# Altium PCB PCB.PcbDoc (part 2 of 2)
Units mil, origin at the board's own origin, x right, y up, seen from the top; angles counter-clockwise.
Board outline 1610 x 1385 mil, 4 copper layers (Top Layer, Signal Layer 1, Signal Layer 2, Bottom Layer), stack 61.2 mil thick; 53 components, 26 nets, 134 pads, 40 vias.
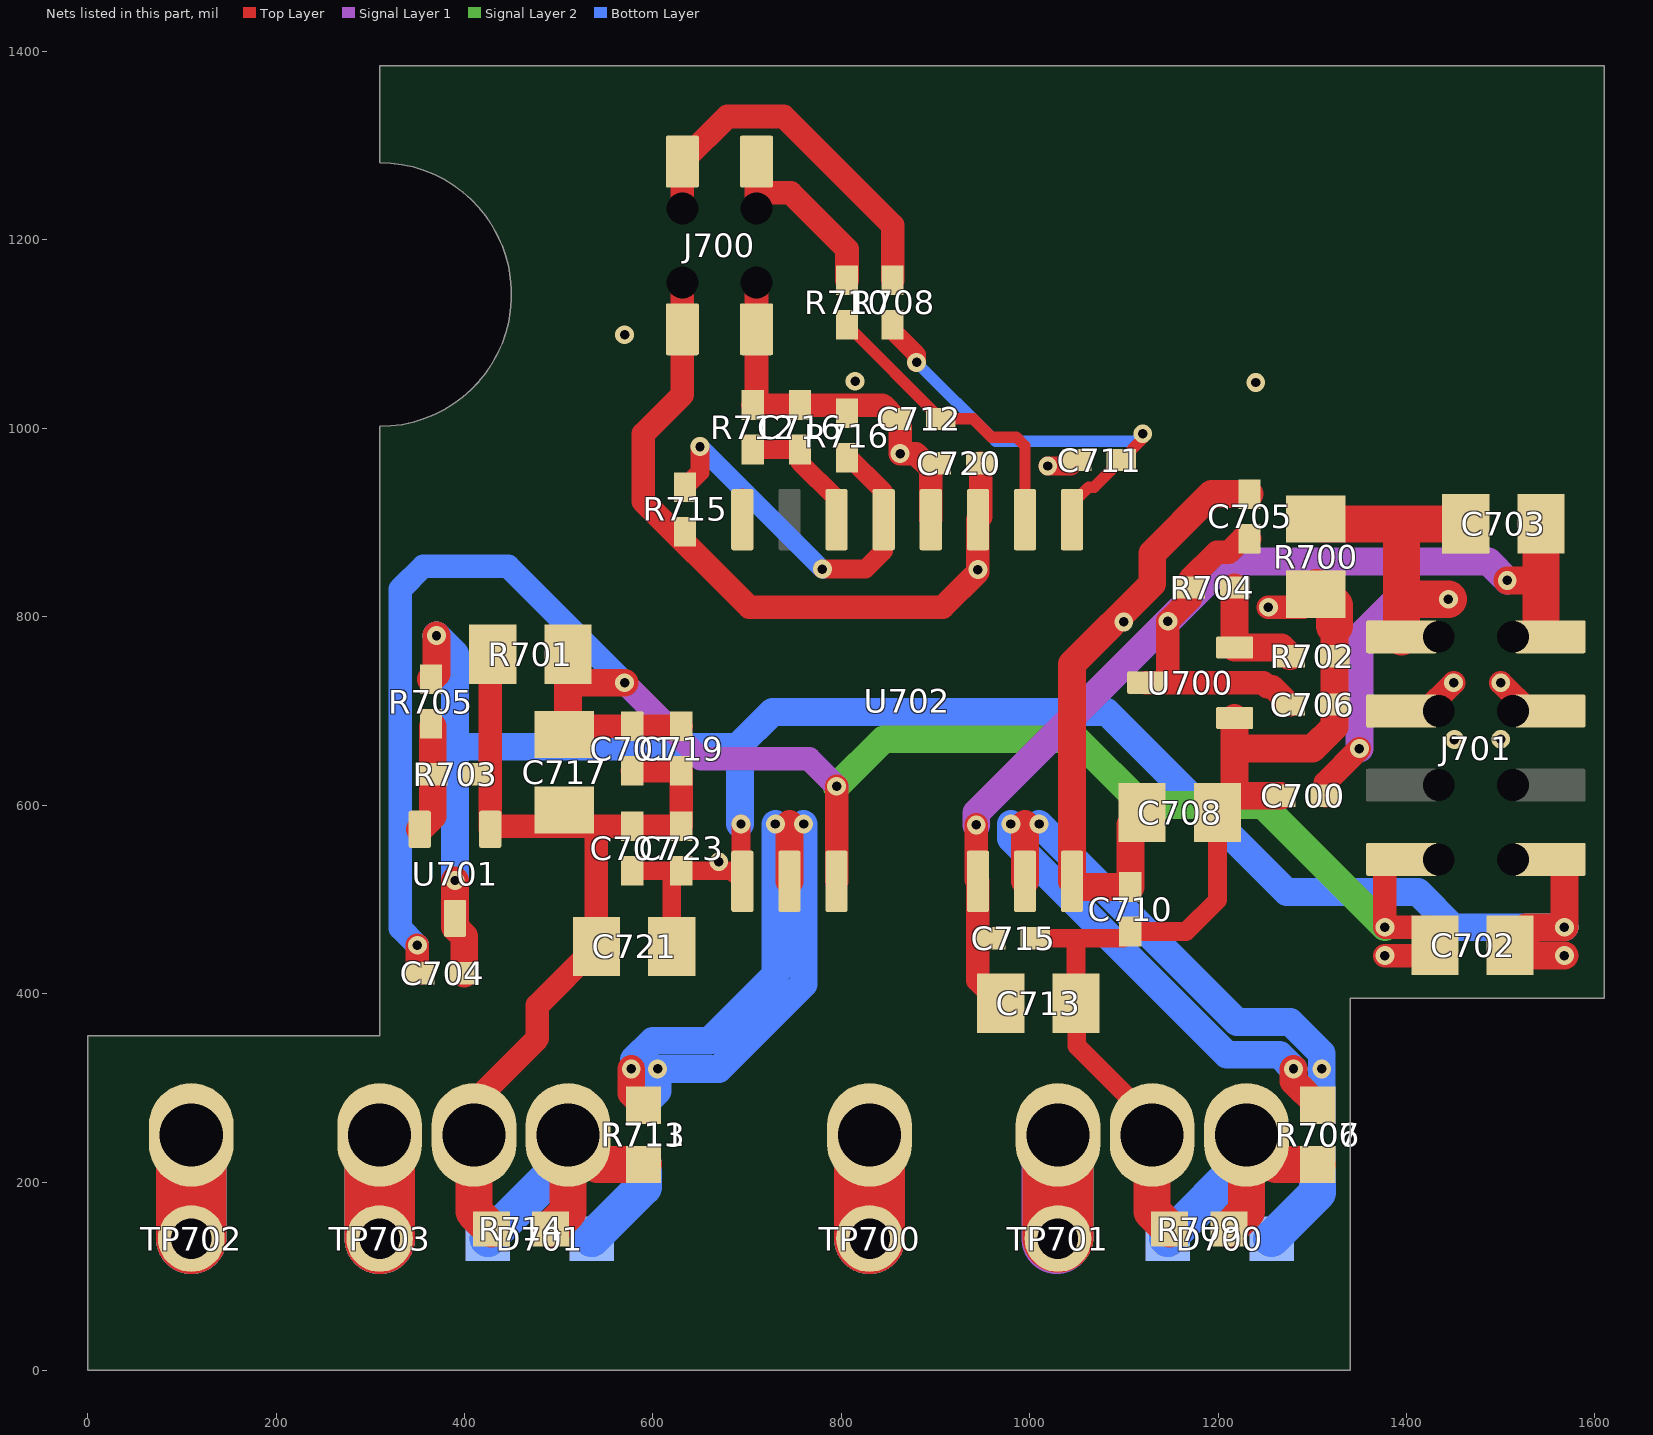
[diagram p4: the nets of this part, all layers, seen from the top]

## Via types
v1: diameter 20, hole 10, Top Layer to Bottom Layer, 40 vias

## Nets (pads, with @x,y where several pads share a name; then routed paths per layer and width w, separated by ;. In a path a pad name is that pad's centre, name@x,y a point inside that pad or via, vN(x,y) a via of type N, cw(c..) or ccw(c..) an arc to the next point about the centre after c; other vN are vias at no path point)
5Vp: C720.1 J700.2 J700.@631.26,1154.71 J701.4 pad.1@1434.13,699.99 R715.2 U702.3 U702.8 | length 850.8
  Top Layer w20: U702.8@693.58,904.42 U702.8@695,903 U702.8@695,926.07
  Top Layer w25: J700.@631.26,1154.71 J700.2@631.26,1105.1 631.26,1035.41 590,994.15 590,922.46 702.46,810 907.49,810 945,847.51 v1(945,850) U702.3@945,903 948.14,906.14 C720.1@948.14,963 ; J701.4@1419.99,699.99 v1(1450,730)
  other v1: 1450.81,669.61 570,1099.23
+VA: C700.1 C703.1 C705.1 C708.1 C710.1 J701.2 pad.1@1434.13,778.73 R700.2 U702.16 | length 1256.9
  Top Layer w25: C700.1@1313.62,610 1313.62,623.62 v1(1350,660)
  Top Layer w29.53: U702.16@1045,519.14 1045,749.98 1130,834.98 1130,867.2 1192.92,930.12 C705.1@1233.34,930.12 ; U702.16@1050.94,513.21 C710.1@1106.82,513.21 C708.1@1106.82,579.62
  Top Layer w39.37: R700.2@1303.78,903.83 1309.07,898.54 1394.56,898.54 ; J701.2@1394.56,778.73 1394.56,898.54 ; 1398.05,818.54 v1(1444.37,818.54) ; C703.1@1462.87,898.54 1394.56,898.54
  Signal Layer 1 w29.53: v1(1350,660) 1350,778.54 1390,818.54 v1(1444.37,818.54)
  other v1: 1099.86,794.59
+VB: C701.1 C702.1 C704.1 C717.1 C719.1 J701.8 pad.1@1434.13,542.51 R701.2 U702.11 | length 2187.7
  Top Layer w25: v1(350,451.35) 350,424.06 C704.1@352.6,421.46 ; C717.1@510,679 514.62,683.62 C701.1@578.19,683.62 C719.1@630,683.62 ; U702.11@795,519.14 v1(795,620) ; v1(1377.02,440.38) 1416.87,440.38 1436,459.51 1425.13,470.38 v1(1377.02,470.38) J701.8@1377.02,532.22
  Top Layer w29.53: C717.1@510,679 R701.2@510,730 ; R701.2@520,730 v1(570,730)
  Signal Layer 1 w25: v1(570,730) 650.83,649.17 765.83,649.17 v1(795,620)
  Signal Layer 2 w29.53: v1(795,620) 845,670 1050,670 1120,600 1247.4,600 v1(1377.02,470.38)
  Bottom Layer w25: v1(350,451.35) 332,469.35 332,829.35 356.25,853.61 446.39,853.61 v1(570,730)
-VA: C703.2 C705.2 C706.2 C713.2 C715.2 J701.1 pad.1@1512.87,778.73 R704.1 U700.3 U702.14 | length 1391.3
  Top Layer w25: v1(943.31,579) 943.31,520.84 U702.14@945,519.14 945,414.07 C713.2@969.21,389.86 ; U700.3@1123.04,730 1248.01,730 1252.19,725.82 1257.28,725.82 C706.2@1276.38,706.72 ; 1146.66,735.01 v1(1146.66,795.18) 1170.29,818.81 R704.1@1170.29,830.93 1170.29,840.06 1198.78,868.54 1211.39,868.54 1225.72,882.87 C705.2@1233.34,882.87
  Top Layer w29.53: v1(1506.87,838.54) 1534.32,838.54
  Top Layer w39.37: J701.1@1542.87,788.3 C703.2@1542.87,898.54
  Signal Layer 1 w29.53: v1(943.31,579) 943.31,591.83 v1(1146.66,795.18) 1210.02,858.54 1486.87,858.54 v1(1506.87,838.54)
-VB: C702.2 C704.2 C707.2 C721.2 C723.2 J701.7 pad.1@1512.87,542.51 R705.1 U701.3 U702.9 | length 2233.3
  Top Layer w20: C707.2@578.19,530.38 C723.2@630,530.38 ; C721.2@620,450 620,520.38 C723.2@630,530.38 ; v1(693.58,580) U702.9@693.58,520.56 ; U702.9@695,519.14 U702.9@693.58,520.56 ; C723.2@630,530.38 683.77,530.38 U702.9@693.58,520.56
  Top Layer w29.53: R705.1@364.41,733.62 370.31,739.53 v1(370.31,780) ; v1(390,520) U701.3@390,479.9 390,470.71 399.84,460.87 C704.2@399.84,421.46 ; v1(1567.5,440.38) 1535.13,440.38 1516,459.51 1526.87,470.38 v1(1567.5,470.38) J701.7@1567.5,540.68
  Bottom Layer w29.53: v1(370.31,780) 390,760.31 v1(390,520) ; 398,662 690,662 ; v1@692.6,580 692.6,659.4 690,662 ; v1(1567.5,470.38) 1449.52,470.38 1412.12,507.78 1272.83,507.78 1081.73,698.88 726.88,698.88 690,662
  other v1: 670,540
Coma: C700.2 C706.1 C708.2 C710.2 C713.1 C715.1 pad.1@1130,250 R700.1 R702.2 R709.1 U700.1 | length 1070.5
  Top Layer w20: C715.1@1005.91,458.72 1099.58,458.72 C710.2@1106.82,465.96 1165.96,465.96 1199.34,499.34 C708.2@1199.34,592.14 ; 1049.21,457 C713.1@1049.21,389.86 1050,389.07 1050,344.5 pad.1@1130,264.5
  Top Layer w25: v1(1253.28,810.13) R700.1@1290.08,810.13
  Top Layer w29.53: C708.2@1199.34,592.14 C708.2@1217.2,610 ; U700.1@1217.53,692.6 1217.53,660 ; C700.2@1266.38,610 C708.2@1217.2,610 ; 1323.62,790 C706.1@1323.62,706.72 1323.62,683.31 1300.31,660 1217.53,660 ; C708.2@1217.2,610 1217.53,610.33 1217.53,660
  Top Layer w39.37: pad.1@1130,218.5 1130,168.5 R709.1@1148.5,150 ; R700.1@1304.46,830.93 1323.62,811.77 1323.62,790
Comb: C701.2 C707.1 C717.2 C719.2 C721.1 C723.1 pad.1@410,250 R701.1 R703.2 R714.1 U701.1 | length 992.8
  Top Layer w25: pad.1@410,250 410,285 477.46,352.46 477.46,387.46 C721.1@540,450 540,571.62 546,577.62 ; R701.1@430,760 427.4,757.4 U701.1@427.4,574.39 430.64,577.62 546,577.62 ; C701.2@578.19,636.38 C719.2@630,636.38 C723.1@630,577.62 C707.1@578.19,577.62 546,577.62
  Top Layer w39.37: pad.1@410,250 410,168.5 R714.1@428.5,150
NetC711_1: C711.1 R708.2 U702.1 | length 454.1
  Top Layer w12: U702.1@1045,903 1045,919.88 1062.57,937.45 1068.35,937.45 C711.1@1097.24,966.35 1120.02,989.12 v1(1120.02,994.15)
  Top Layer w20: R708.2@854.41,1110 854.41,1103.7 880,1078.11 v1(880,1070)
  Bottom Layer w12: v1(880,1070) 963.63,986.37 1112.24,986.37 v1(1120.02,994.15)
NetC712_1: C712.1 R710.2 U702.2 | length 338.8
  Top Layer w12: R710.2@806.05,1109.54 C712.1@905.59,1010 940,1010 959.48,990.52 985.85,990.52 995,981.37 U702.2@995,903
  Top Layer w20: U702.2@995,884.61 U702.2@995,903
NetC716_1: C716.1 R712.2 U702.6 | length 127.1
  Top Layer w20: R712.2@706.05,977.45 C716.1@756.05,977.45 ; C716.1@756.05,963.95 795,925 U702.6@795,903
NetD700_1: D700.1 R707.2 | length 98.8
  Bottom Layer w39.37: D700.1@1256.77,140 1305.66,188.88 R707.2@1305.66,218.5
NetD701_1: D701.1 R713.2 | length 101.2
  Bottom Layer w39.37: D701.1@535.12,140 590,194.88 R713.2@590,218.5
NetR702_1: R702.1 R704.2 U700.2 | length 126.3
  Top Layer w29.53: R704.2@1217.53,830.93 U700.2@1217.53,767.4 1266.98,767.4 R702.1@1276.38,758
NetR703_1: R703.1 R705.2 U701.2 | length 114.9
  Top Layer w29.53: U701.2@352.6,574.39 366.38,588.17 R703.1@366.38,632.8 R705.2@366.38,683.62
NetR706_1: R706.1 R707.1 U702.15 | length 984.5
  Top Layer w29.53: U702.15@995,519.14 995,580 ; v1(1280,320) 1280,307.15 R706.1@1305.66,281.5
  Bottom Layer w29.53: v1(980,580) 980,564.48 1209.48,335 1265,335 v1(1280,320) ; v1(1010,580) 1220,370 1276.52,370 1310,336.52 v1(1310,320) 1310,285.84 R707.1@1305.66,281.5
NetR711_1: R711.1 R713.1 U702.10 | length 859
  Top Layer w29.53: v1(577,320) 577,294.5 R711.1@590,281.5 ; U702.10@745,519.14 745,580
  Bottom Layer w29.53: 580,330 600,350 660,350 730,420 v1(730,580) ; R713.1@590,281.5 604.99,296.49 v1(604.99,320) 670,320 760,410 v1(760,580)
NetR715_1: R715.1 R716.2 U702.5 | length 395.6
  Top Layer w20: R715.1@634.11,937.45 650,953.34 v1(650,980.6) ; v1(780,850.6) 825.6,850.6 845,870 U702.5@845,903 ; R716.2@806.05,971.4 U702.5@845,932.45
  Bottom Layer w20: v1(650,980.6) v1(780,850.6) v1@780.6,850
PGND: C711.2 C712.2 C716.2 C720.2 J700.4 J700.@710,1154.71 J701.3 pad.1@1512.87,699.99 R712.1 R716.1 U702.4 | length 508.9
  Top Layer w20: v1(1019.13,960) 1043.65,960 C711.2@1050,966.35
  Top Layer w25: R712.1@706.05,1024.69 806.05,1024.69 843.65,1024.69 C712.2@858.35,1010 ; R712.1@710,1028.65 J700.4@710,1105.1 J700.@710,1154.71 ; C712.2@862.42,1005.93 v1(862.42,973.2) 878.91,973.2 895,957.11 U702.4@895,903 ; v1(1500,730) 1530.01,699.99 J701.3@1552.44,699.99
  other v1: 1500,670 1240,1048.6 814.71,1050
VDA: pad.1@830,250 TP700.1 | length 440
  Top Layer w75: TP700.1@830,140 pad.1@830,250
  Signal Layer 1 w75: TP700.1@830,140 pad.1@830,250
  Signal Layer 2 w75: TP700.1@830,140 pad.1@830,250
  Bottom Layer w75: TP700.1@830,140 pad.1@830,250
VDB: pad.1@110,250 TP702.1 | length 440
  Top Layer w75: TP702.1@110,140 pad.1@110,250
  Signal Layer 1 w75: TP702.1@110,140 pad.1@110,250
  Signal Layer 2 w75: TP702.1@110,140 pad.1@110,250
  Bottom Layer w75: TP702.1@110,140 pad.1@110,250
Vg1: J700.1 J700.@631.26,1233.45 R708.1 | length 398.8
  Top Layer w25: J700.@631.26,1233.45 J700.1@631.26,1283.05 679.19,1330.99 739.01,1330.99 854.41,1215.59 R708.1@854.41,1157.24
Vg2: J700.3 J700.@710,1233.45 R710.1 | length 203.4
  Top Layer w25: J700.@710,1233.45 710,1250 ; J700.3@710,1283.05 710,1250 ; R710.1@806.05,1157.24 806.05,1190.16 746.2,1250 710,1250
VGA: D700.2 pad.1@1230,250 R706.2 R709.2 | length 314.4
  Top Layer w39.37: R709.2@1211.5,150 1230,168.5 pad.1@1230,250 1261.5,218.5 R706.2@1305.66,218.5
  Bottom Layer w39.37: D700.2@1146.54,140 pad.1@1230,223.46
VGB: D701.2 pad.1@510,250 R711.2 R714.2 | length 321.1
  Top Layer w39.37: R714.2@491.5,150 510,168.5 pad.1@510,250 541.5,218.5 R711.2@590,218.5
  Bottom Layer w39.37: D701.2@424.88,140 pad.1@510,225.12
VSA: pad.1@1030,250 TP701.1 | length 434.2
  Top Layer w75: TP701.1@1030,141.46 pad.1@1030,250
  Signal Layer 1 w75: TP701.1@1028.54,140 pad.1@1028.54,248.54
  Signal Layer 2 w75: TP701.1@1030,141.46 pad.1@1030,250
  Bottom Layer w75: TP701.1@1030,141.46 pad.1@1030,250
VSB: pad.1@310,250 TP703.1 | length 440
  Top Layer w75: TP703.1@310,140 pad.1@310,250
  Signal Layer 1 w75: TP703.1@310,140 pad.1@310,250
  Signal Layer 2 w75: TP703.1@310,140 pad.1@310,250
  Bottom Layer w75: TP703.1@310,140 pad.1@310,250
pads on no net: J701.5 J701.6 U702.7

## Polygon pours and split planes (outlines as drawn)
5Vp on Top Layer "5Vp" (solid, pour order 0): 1363.56,659.4 1457.12,659.4 1462.87,665.15 1462.87,730 1452.87,740 1414.18,740 1363.56,689.37
+VB on Top Layer "+VB" (solid, pour order 2): 1360,560 1350,550 1350,420 1360,410 1440,410 1450,420 1450,550 1440,560
-VB on Top Layer "-VB" (solid, pour order 4): 1500,410 1490,420 1490,550 1500,560 1580,560 1590,550 1590,420 1580,410
-VA on Top Layer "-VA" (solid, pour order 6): 1530,950 1520,940 1520,868.54 1500,848.54 1496.87,848.54 1496.87,783.13 1520,760 1590,760 1600,770 1600,940 1590,950
Coma on Top Layer "COMA" (solid, pour order 8): 1160,110 1170,120 1170,250 1170.29,332.28 1280,441.99 1280,611.48 1350,681.48 1350,840 1340,850 1217.69,850 1206.1,838.41 1206.1,709.81 1180,683.71 1180,530 1130,480 1010.78,480 996.07,465.29 996.07,433.79 1020,409.86 1020,357.87 1087.87,290 1087.87,122.13 1100,110
PGND on Top Layer "PGND" (solid, pour order 14): 1500,740 1490,730 1490,666.27 1496.27,660 1560,660 1590,690 1590,720 1570,740
+VA on Top Layer "+VA" (solid, pour order 16): 1480,870 1490,880 1490,940 1449.4,980.6 1210.89,980.6 1170.29,940 1115.23,884.94 1115.23,839.64 1031.48,755.89 1031.48,513 1045.14,499.34 1109.34,499.34 1150,540 1150,699.87 1217.53,767.4 1467.4,767.4 1480,780
Comb on Top Layer "COMB" (solid, pour order 26): 410,783.73 410,740 400,730 400,557.78 427.4,530.38 427.4,397.4 370.31,340.31 370.31,160.69 401,130 439.49,130 450,140.51 450,280 560,390 560,553.62 566.38,560 624.35,560 640,575.65 640,640 630,650 566.54,650 551.54,635 481,635 466,650 466,777.73 460,783.73
VGB on Top Layer "VGB" (solid, pour order 28): 480,289.62 470,279.62 470,141.3 480,131.3 552.32,131.3 610,188.98 610,220 590,240 570,240 570,240.44 520,290.44
VGA on Top Layer "VGA" (solid, pour order 30): 1199.73,120.27 1190.16,129.84 1190,263.24 1217.2,290.44 1218.02,289.62 1250,289.62 1250,286.96 1286.96,250 1324.36,250 1334.2,240 1334.2,184.2 1270.27,120.27
5Vp on Top Layer "5VP" (solid, pour order 32): 670,1160 660,1170 589.73,1170 560,1140.27 560,920.93 683.16,797.77 923.47,797.77 960,834.29 960,930 926.96,963.04 918.93,963.04 918.93,961.97 916.96,960 918.93,958.03 918.93,857.96 891.2,830.22 891.2,829.42 744.14,829.42 710,863.56 710,920.6 670,960.6
PGND on Top Layer "PGND" (solid, pour order 40): 700,1170 690,1160 690,1019.83 700,1009.83 700.17,1010 790,1010 870,930 870,880 880,870 900,870 910,880 910,989.37 730,1169.37
+VB on Top Layer "+VB" (solid, pour order 54): 490,788.54 480,778.54 480,678.31 497.72,660.59 530,660.59 530.59,660 640,660 690,610 750.15,610 780,580.15 780,500 790,490 810,490 820,500 820,629.47 729.47,720 645.3,720 577,788.3
-VB on Top Layer "-VB" (solid, pour order 58): 710,579.62 699.62,590 677.81,590 641.81,554 570.38,554 566.38,550 566.38,492.17 580,478.54 580,433.44 591.99,421.46 629.39,421.46 710,502.07
NetR711_1 on Top Layer "R711_1" (solid, pour order 60): 720,590 710,580 710,490.31 559.65,339.96 559.65,270 569.65,260 608.7,260 639.04,290.33 770,421.3 770,576.05 756.05,590
-VA on Top Layer "-VA" (solid, pour order 62): 952.14,600 960,592.14 960,516.42 980,496.42 980,457.07 1000,437.07 1000,359.86 990,349.86 940.14,349.86 930,360 930,593.36 936.64,600
-VB on Bottom Layer "-VB" (solid, pour order 38): 1580,410 1490,410 1444.41,455.59 1444.41,460 1404.35,500 1220,500 1070,650 771.15,650 710,588.85 710,550 660,500 382.14,500 360,522.14 360,810 440,730 1122,730 1295.11,556.89 1571.46,556.89 1590.33,538.02 1590.33,420
NetR706_1 on Bottom Layer "R706_1" (solid, pour order 36): 980,600 970,590 970,556.89 970.41,556.89 1202.29,325 1254.19,325 1293.35,285.84 1317.61,285.84 1321.77,290 1321.77,345.26 1287.02,380 1230,380 1010,600
NetR711_1 on Bottom Layer "R711_1" (solid, pour order 34): 730,600 720,590 720,430 650,360 593.48,360 562.8,329.32 562.8,268.5 571.3,260 630,260 775.04,405.04 775.04,590.7 765.74,600
+VB on Bottom Layer "+VB" (solid, pour order 10): 1360,560 1305.66,505.66 1305.66,464.34 1360,410 1440,410 1450,420 1450,550 1440,560
PGND on Bottom Layer "PGND" (solid, pour order 44): 680,1160 680,1146.85 680,1146.33 680,1051.51 842.09,889.42 1290,889.42 1290,866.27 1496.27,660 1570,660 1600,690 1600,1120 1350,1370 890,1370
5Vp on Bottom Layer "5VP" (solid, pour order 18): 1457.12,659.4 1462.59,664.88 1462.59,757.41 1310,910 880,910 670,1120 670,1160 660,1170 589.73,1170 580,1160.27 580,1070 820,830 1243.76,830 1414.35,659.4
NetR711_1 on Signal Layer 1 "R711_1" (solid, pour order 70): 722.14,590 712.14,580 712.14,490.31 561.79,339.96 561.79,270 571.79,260 610.84,260 641.18,290.33 772.14,421.3 772.14,576.05 758.19,590
Coma on Signal Layer 1 "COMA" (solid, pour order 42): 1160,110 1170,120 1170,250 1170.29,332.28 1280,441.99 1280,611.48 1310,641.48 1310,810 1300,820 1247.53,820 1206.1,778.57 1206.1,709.81 1180,683.71 1180,554.84 1105.16,480 1087.87,462.71 1087.87,290 1087.87,122.13 1100,110
PGND on Signal Layer 1 "PGND" (solid, pour order 46): 680,1160 680,1146.85 680,1146.33 680,1051.51 842.09,889.42 1114.42,889.42 1267.5,1042.5 1131.77,1178.23 698.23,1178.23
-VA on Signal Layer 1 "-VA" (solid, pour order 48): 930,570 935.67,564.33 950,564.33 965.67,580 1070,580 1200,710 1200,808.93 1221.07,830 1520,830 1530,840 1530,900 1520,910 1242.26,910 930,597.74
+VA on Signal Layer 1 "+VA" (solid, pour order 50): 1470,822.03 1469.86,822.03 1461.9,830 1390,830 1340,780 1340,650 1350,640 1383.76,640 1393.76,650 1393.76,734.72 1469.16,810.13
-VB on Signal Layer 1 "-VB" (solid, pour order 72): 710,580 700,590 630,590 420,800 370,800 360,790 360,520 380.42,499.58 652.57,499.58 709.41,556.43
NetR711_1 on Signal Layer 2 "R711_1" (solid, pour order 68): 722.14,590 712.14,580 712.14,490.31 561.79,339.96 561.79,270 571.79,260 610.84,260 641.18,290.33 772.14,421.3 772.14,576.05 758.19,590
+VA on Signal Layer 2 "+VA" (solid, pour order 52): 1080,800.02 1100.02,780 1429.87,780 1460,810.13 1460,840 1380,920 1116.23,920 1080,883.77
+VB on Signal Layer 2 "+VB" (solid, pour order 66): 1390,410 1400,420 1400,500 1238.9,661.1 1113.74,661.1 1044.84,730 634.99,730 604.99,760 500,760 321.1,581.1 321.1,448.9 340,430 620,430 840,650 1031.84,650 1271.84,410

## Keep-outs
Keep-Out Layer:
  text ".Layer_Name" at 577,-858.49 h60

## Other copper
Top Layer:
  text ".Layer_Name" at 577,-858.49 h60
Bottom Layer:
  text ".Layer_Name" at 577,-858.49 h60

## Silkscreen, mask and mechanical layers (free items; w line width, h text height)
Top Overlay:
  lines w10: 340,780 330,790 330,810.83 330.94,811.77 360,811.77 ; 430,470.71 449.06,451.65 449.06,398.36 487.41,360 510,360 ; 541.5,960 541.5,1000 570.14,1028.65 660,1028.65 ; 550,1330 550.14,1330 570.14,1350 736.05,1350 756.05,1330 756.05,1090.5 776.55,1070 845.59,1070 865.59,1050 ; 679.19,450 709.19,420 745,420 ; 900.66,360 910,369.34 910,370 910,420 920,430 ; 1300,961.1 1300,1009.69 1329.38,1039.07 1330.42,1039.07 ; 1320,1380 1320,1049.49 1340.85,1028.65 1600,1028.65
  text ".Layer_Name" at 577,-858.49 h60
Bottom Overlay:
  text "PMP22001 RevA" at 1360,690 h108.27
  text ".Layer_Name" at 577,-858.49 h60
Top Paste:
  text ".Layer_Name" at 577,-858.49 h60
Bottom Paste:
  text ".Layer_Name" at 577,-858.49 h60
Top Solder:
  text ".Layer_Name" at 577,-858.49 h60
  text ".Layer_Name" at 577,-858.49 h60
Bottom Solder:
  text ".Layer_Name" at 577,-858.49 h60
Drill Guide:
  text ".Layer_Name" at 577,-858.49 h60
M1 Board Outline:
  circle w10: c1030,1142 r140
  lines w10: 0,0 1340,0 1340,395 1610,395 1610,1385 310,1385 310,1282 cw(c310,1142) 310,1002 310,355 0,355 0,0
  text ".Layer_Name" at 577,-858.49 h60
M2 Board Dimensions:
  rectangle: 0,-275 125,-150
  rectangle: 125,-400 500,-275
  lines w7: 0,-275 1000,-275 ; 125,-400 125,-150 ; 250,-400 250,-150 ; 500,-400 500,-150 ; 750,-400 750,-150 ; 0,-400 1000,-400 1000,-150 0,-150 0,-400
  text ".Layer_Name" at 577,-858.49 h60
M3 3D STEP Top:
  text ".Layer_Name" at 577,-858.49 h60
M4 3D STEP Bottom:
  text ".Layer_Name" at 577,-858.49 h60
M5 Assembly Top:
  lines w10: -292,-930.17 6308,-930.17 ; -292,-726.83 6310,-726.83 ; -292,-523.5 -292,-1133.5 3713,-1133.5 6310,-1133.5 6310,-523.5 -291.5,-523.5 -291.5,-1133.5 1284,-1133.5 ; 2173,-1133.5 2173,-523.5 ; 3440,-726.83 3440,-523.5 ; 4280,-726.83 4280,-523.5 ; 4902,-1140 4902,-937.17
  text "COMPONENTS MARKED 'DNP' SHOULD NOT BE POPULATED." at 1153.5,-318.5 h60
  text "ASSEMBLY VARIANT:" at 1153,-434 h60
  text ".VariantName" at 2189,-434 h60
  text "PCB VIEWED FROM TOP SIDE" at -228.5,-655.67 h60
  text "BOARD #:" at 2248,-655.67 h60
  text ".PRJ_Number" at 2793.5,-655.67 h60
  text "REV:" at 3638,-655.67 h60
  text ".PCB_Rev" at 3929.5,-655.67 h60
  text "SVN REV:" at 4476,-655.67 h60
  text ".VersionControl_RevNumber" at 4982,-655.67 h60
  text "TID #:" at 2248,-859 h60
  text ".TID" at 2793.5,-859 h60
  text "PLOT NAME =" at -228.5,-1064.34 h60
  text ".plot_File_Name" at 577,-1064.34 h60
  text "GENERATED    :" at 2250,-1064.34 h60
  text ".Print_Date" at 3119.5,-1064.34 h60
  text ".Print_Time" at 3848.5,-1064.34 h60
  text "TEXAS INSTRUMENTS" at 5113,-1064.34 h60
M6 Assembly Bottom:
  lines w10: -292.5,-727.33 6309.5,-727.33 ; -290.5,-930.67 6309.5,-930.67 ; 1115.5,-1140.5 1115.5,-937.67 ; 1737.5,-727.33 1737.5,-524 ; 2577.5,-727.33 2577.5,-524 ; 3844.5,-1134 3844.5,-524 ; 4733.5,-1134 6309,-1134 6309,-524 -292.5,-524 -292.5,-1134 2304.5,-1134 6309.5,-1134 6309.5,-524
  text "COMPONENTS MARKED 'DNP' SHOULD NOT BE POPULATED." at 6102,-318 h60
  text ".VariantName" at 5058,-434 h60
  text "ASSEMBLY VARIANT:" at 6097,-434 h60
  text ".VersionControl_RevNumber" at 1035.5,-656.17 h60
  text "SVN REV:" at 1541.5,-656.17 h60
  text ".PCB_Rev" at 2088,-656.17 h60
  text "REV:" at 2379.5,-656.17 h60
  text ".PRJ_Number" at 3224,-656.17 h60
  text "BOARD #:" at 3769.5,-656.17 h60
  text "PCB VIEWED FROM BOTTOM SIDE" at 6246,-656.17 h60
  text ".TID" at 3224,-859.5 h60
  text "TID #:" at 3769.5,-859.5 h60
  text "TEXAS INSTRUMENTS" at 904.5,-1064.84 h60
  text ".Print_Time" at 2169,-1064.84 h60
  text ".Print_Date" at 2898,-1064.84 h60
  text "GENERATED    :" at 3767.5,-1064.84 h60
  text ".plot_File_Name" at 5440.5,-1064.84 h60
  text "PLOT NAME =" at 6246,-1064.84 h60
M9 Title Sheet:
  drawing of 57 lines, arcs and shapes, not listed
  text "1" at 739.84,8036.5 h70
  text "2" at 3235.5,8036.5 h70
  text "3" at 5724.84,8036.5 h70
  text "4" at 8231.51,8036.5 h70
  text "5" at 10730.5,8036.5 h70
  text "6" at 13235.5,8036.5 h70
  text "A" at -416.5,6893.5 h70
  text "A" at 14383.5,6893.5 h70
  text "B" at -416.5,4513.5 h70
  text "B" at 14383.5,4513.5 h70
  text "C" at -416.5,2138.5 h70
  text "C" at 14383.5,2138.5 h70
  text "PROJECT TITLE:" at 11343.5,277.5 h45
  text ".PRJ_Title" at 11393.5,144.17 h70
  text "DESIGNED FOR:" at 11343.5,-23.5 h45
  text ".PRJ_Customer" at 11393.5,-163.5 h70
  text "D" at -416.5,-231.5 h70
  text "D" at 14383.5,-231.5 h70
  text "FILE NAME:" at 11343.5,-323.5 h45
  text ".PCB_File_Name_No_Path" at 11393.5,-443.5 h70
  text "Texas Instruments (TI) and/or its licensors do not warrant the accuracy or completeness of this specification" at 6374,-605.34 h45
  text "ENGINEER:" at 11343.5,-613.5 h45
  text "LAYOUT BY:" at 12848.5,-613.5 h45
  text "or any information contained therein. TI and/or its licensors do not warrant that this design will meet" at 6329.01,-718 h45
  text ".PRJ_Engineer" at 11393.5,-768.49 h70
  text ".PCB_Layout" at 12899,-768.49 h70
  text "the specifications, will be suitable for your application or fit for any particular purpose, or will operate in" at 6329.01,-830.67 h45
  text ".Layer_Name" at 577,-858.49 h60
  text "ALTIUM DESIGNER VERSION:" at 12848.5,-923.5 h45
  text "an implementation. TI and/or its licensors do not warrant that the design is production worthy. You should" at 6329.01,-943.33 h45
  text "completely validate and test your design implementation to confirm the system functionality for your application." at 6374,-1056 h45
  text ".print_Scale" at 11393.5,-1056.83 h70
  text ".Application_BuildNumber" at 12899,-1056.83 h70
  text "1" at 739.84,-1263.5 h70
  text "2" at 3235.5,-1263.5 h70
  text "3" at 5724.84,-1263.5 h70
  text "4" at 8231.51,-1263.5 h70
  text "5" at 10730.5,-1263.5 h70
  text "6" at 13235.5,-1263.5 h70
M10 Fab Notes:
  drawing of 189 lines, arcs and shapes, not listed
  text "DESIGN INFORMATION" at 12382.02,6356.17 h60
  text "MIN. TRACK WIDTH:" at 11737.46,6224.05 h60
  text "8" at 12833.7,6224.05 h60
  text "MIL" at 12988.46,6224.05 h60
  text "MIN. CLEARANCE:" at 11737.46,6099.92 h60
  text "0.2" at 12773.7,6099.93 h60
  text "mm" at 12988.46,6099.92 h60
  text "MIN. VIA PAD SIZE:" at 11737.46,5975.8 h60
  text "24" at 12803.71,5975.8 h60
  text "MIL" at 12988.46,5975.8 h60
  text "0.05mm (2MIL)" at 12432.46,5845.9 h60
  text "MINIMUM ANNULAR RING" at 11408.23,5837.67 h60
  text "EXTERNAL" at 13140.46,5837.67 h60
  text "PER" at 11608.23,5727.55 h60
  text "IPC-D-275 CLASS 2 LEVEL C" at 11828.23,5727.54 h60
  text "MIL, HOLES" at 13316.46,5627.07 h60
  text "+/-" at 12924,5618.48 h60
  text "+/-" at 13778,5618.48 h60
  text "REGISTRATION TOLERANCES:" at 11408.23,5617.42 h60
  text "METAL" at 12608,5617.42 h60
  text "5" at 13184.2,5617.42 h60
  text "3" at 14017.2,5617.42 h60
  text "MIL" at 14133.46,5617.42 h60
  text "HOLE SIZE TOLERANCE (UNLESS OTHERWISE SPECIFIED):" at 11408.23,5519.1 h60
  text "+/-" at 13778,5516.23 h60
  text "3" at 14017.2,5515.17 h60
  text "MIL" at 14133.46,5515.17 h60
  text "MATERIAL:" at 11333.46,5377.52 h60
  text "FR-4 High Tg" at 12319.9,5249 h60
  text "X" at 12175.46,5241.01 h60
  text "FR-408" at 11754.46,5236.49 h60
  text "OTHER" at 13242.46,5236.49 h60
  text "62 MIL (1.6mm) +/-10%" at 12074.56,5093.46 h60
  text "X" at 11954.46,5091.01 h60
  text "THICKNESS:" at 11408.23,5085.24 h60
  text "OTHER" at 13359.46,5085.24 h60
  text "TOLERANCE:" at 11408.23,4946.92 h60
  text "X" at 12256.46,4946.92 h60
  text "ANSI IPC-6012 TYPE 3 CLASS 2" at 12434.48,4946.92 h60
  text "OTHER +/-" at 12434.46,4802.73 h60
  text "BOW & TWIST:" at 11408.23,4657.54 h60
  text "X" at 12256.46,4657.54 h60
  text "ANSI IPC-6012 TYPE 3 CLASS 2" at 12434.48,4657.54 h60
  text "OTHER +/-" at 12434.46,4510.85 h60
  text "DRILLING:" at 11333.46,4380.23 h60
  text "NC_DRILL FILES" at 13094.46,4275.04 h60
  text "REFERENCE:" at 11408.23,4271.1 h60
  text "X" at 12065.46,4271.01 h60
  text "AS SHOWN" at 12243.46,4271.1 h60
  text "X" at 12966.46,4271.1 h60
  text "OTHER" at 13392.46,4128.85 h60
  text "PTH COPPER THICKNESS:" at 11407.91,4125.32 h60
  text "X" at 12547.14,4125.32 h60
  text "20-30 um" at 12675.14,4125.32 h60
  text "BOARD FINISH:" at 11333.46,3977.73 h60
  text "SILKSCREEN:" at 11488.68,3867.6 h60
  text "X" at 12446.46,3867.6 h60
  text "TOP" at 12563.46,3867.6 h60
  text "X" at 12956.46,3867.6 h60
  text "BOTTOM" at 13074.46,3867.6 h60
  text "SILKSCREEN COLOR:" at 11488.68,3712.41 h60
  text "X" at 12445.46,3712.41 h60
  text "WHITE" at 12563.46,3712.41 h60
  text "OTHER" at 13074.46,3712.41 h60
  text "X" at 12576.46,3568.96 h60
  text "GREEN" at 12694.46,3568.96 h60
  text "OTHER" at 13312.46,3568.96 h60
  text "SOLDER RESIST COLOR:" at 11488.68,3562.1 h60
  text "X" at 12576.46,3414.71 h60
  text "MATTE" at 12694.46,3414.71 h60
  text "SEMI-GLOSS" at 13312,3414.07 h60
  text "IMMERSION GOLD (ENIG)" at 12394.46,3241.94 h60
  text "ENEPIG" at 13732,3234.72 h60
  text "SURFACE FINISH:" at 11333.46,3233.72 h60
  text "X" at 12216.46,3233.72 h60
  text "IMM. TIN/SILVER OR EQUIV" at 11663,3096.4 h60
  text "OTHER" at 13094.46,3092.47 h60
  text "ARRAY/PANEL:" at 11333.46,2937.09 h60
  text "CUT AND TRIM PER M1 BOARD OUTLINE" at 12394.46,2928.87 h60
  text "N.C. ROUTE" at 12394.46,2792.9 h60
  text "X" at 13082.46,2792.9 h60
  text "V. SCORE" at 13260.46,2792.9 h60
  text "CERTIFICATION:" at 11333.46,2663.77 h60
  text "MATERIALS AND WORKMANSHIP FOR ALL PCBS" at 12058.46,2663.77 h60
  text "TO MEET OR EXCEED THE REQUIREMENTS OF:" at 12058.46,2569.71 h60
  text "X" at 11695.97,2441.08 h60
  text "ANSI IPC-A-600F CLASS ->" at 11823.96,2441.08 h60
  text "X" at 13471.97,2441.08 h60
  text "2" at 13581.96,2441.08 h60
  text "1" at 13266.96,2439.58 h60
  text "3" at 13935.96,2439.58 h60
  text "X" at 12507.97,2293.39 h60
  text "RoHS" at 12635.96,2293.39 h60
  text "OTHER" at 13280.36,2293.39 h60
  text "PER ORDER" at 13677.42,2293.39 h60
  text "ALL BOARDS MUST MEET OR EXCEED UL94-V0 REQUIREMENTS." at 11361,2139.57 h60
  text "PCB MUST BEAR THE UL94V-0 UL REGISTERED MATERIAL ID NUMBER" at 11361,2023.5 h60
  text "ADDITIONAL REQUIREMENTS:" at 11333.46,1854.08 h60
  text "MICROSECTION:" at 11408.23,1746.95 h60
  text "YES" at 12313.96,1746.95 h60
  text "REQUIRED" at 13175.46,1602.62 h60
  text "BARE BOARD ELEC. TEST:" at 11408.23,1599.76 h60
  text "NONE" at 12713.96,1599.76 h60
  text "X" at 13057.46,1599.76 h60
  text "PER ORDER" at 13767.46,1599.76 h60
  text "XX MIL VIAS REQUIRE NON-CONDUCTIVE FILL AND PLANARIZE" at 11576.38,1394.82 h59
  text "XX MIL VIAS REQUIRE CONDUCTIVE FILL AND PLANARIZE" at 11584.38,1290.84 h60
  text "OUTER XX MIL TRACES REQUIRE 50 OHM SINGLE-ENDED IMPEDANCE" at 11583.39,1127.46 h58
  text "LAYER 2 & 3 (INNER LAYERS) XX MIL WIDE, XX MIL SPACE / TRACES REQUIRE 100 OHM DIFFERENTIAL IMPEDANCE" at 11575.39,891.74 h60
  text ".Layer_Name" at 577,-858.49 h60
M11 Gerber Information:
  lines w10: -292,-930.17 6308,-930.17 ; -292,-726.83 6310,-726.83 ; -292,-523.5 -292,-1133.5 3713,-1133.5 6310,-1133.5 6310,-523.5 -291.5,-523.5 -291.5,-1133.5 1284,-1133.5 ; 2173,-1133.5 2173,-523.5 ; 3440,-726.83 3440,-523.5 ; 4280,-726.83 4280,-523.5 ; 4902,-1140 4902,-937.17
  text "ALL ARTWORK VIEWED FROM TOP SIDE" at -228.5,-655.67 h60
  text "BOARD #:" at 2248,-655.67 h60
  text ".PRJ_Number" at 2793.5,-655.67 h60
  text "REV:" at 3638,-655.67 h60
  text ".PCB_Rev" at 3929.5,-655.67 h60
  text "SVN REV:" at 4476,-655.67 h60
  text ".VersionControl_RevNumber" at 4982,-655.67 h60
  text "LAYER NAME =" at -228.5,-858.49 h60
  text "TID #:" at 2248,-859 h60
  text ".TID" at 2793.5,-859 h60
  text "PLOT NAME =" at -228.5,-1064.34 h60
  text ".plot_File_Name" at 577,-1064.34 h60
  text "GENERATED    :" at 2250,-1064.34 h60
  text ".Print_Date" at 3119.5,-1064.34 h60
  text ".Print_Time" at 3848.5,-1064.34 h60
  text "TEXAS INSTRUMENTS" at 5113,-1064.34 h60
M12 Stackup:
  drawing of 295 lines, arcs and shapes, not listed
  text "Layer" at 6590.58,7650 h60
  text "Name" at 7000.49,7650 h60
  text "Material" at 7940.23,7650 h60
  text "Thickness" at 8800,7650 h60
  text "Constant" at 9449.84,7650 h60
  text "Board Layer Stack" at 10019.7,7650 h60
  text "1" at 6590.58,7530 h60
  text "Top Overlay" at 7000.49,7530 h60
  text "2" at 6590.58,7410 h60
  text "Top Solder" at 7000.49,7410 h60
  text "Solder Resist" at 7940.23,7410 h60
  text "0.40mil" at 8800,7410 h60
  text "3.5" at 9449.84,7410 h60
  text "3" at 6590.58,7290 h60
  text "Top Layer" at 7000.49,7290 h60
  text "Copper" at 7940.23,7290 h60
  text "1.40mil" at 8800,7290 h60
  text "4" at 6590.58,7170 h60
  text "Dielectric 3" at 7000.49,7170 h60
  text "7.80mil" at 8800,7170 h60
  text "4.2" at 9449.84,7170 h60
  text "5" at 6590.58,7050 h60
  text "Signal Layer 1" at 7000.49,7050 h60
  text "Copper" at 7940.23,7050 h60
  text "1.40mil" at 8800,7050 h60
  text "6" at 6590.58,6930 h60
  text "Dielectric 2" at 7000.49,6930 h60
  text "FR-4" at 7940.23,6930 h60
  text "40.00mil" at 8800,6930 h60
  text "4.2" at 9449.84,6930 h60
  text "7" at 6590.58,6810 h60
  text "Signal Layer 2" at 7000.49,6810 h60
  text "Copper" at 7940.23,6810 h60
  text "1.40mil" at 8800,6810 h60
  text "8" at 6590.58,6690 h60
  text "Dielectric 4" at 7000.49,6690 h60
  text "7.80mil" at 8800,6690 h60
  text "4.2" at 9449.84,6690 h60
  text "9" at 6590.58,6570 h60
  text "Bottom Layer" at 7000.49,6570 h60
  text "Copper" at 7940.23,6570 h60
  text "1.40mil" at 8800,6570 h60
  text "10" at 6590.58,6450 h60
  text "Bottom Solder" at 7000.49,6450 h60
  text "Solder Resist" at 7940.23,6450 h60
  text "0.40mil" at 8800,6450 h60
  text "3.5" at 9449.84,6450 h60
  text "11" at 6590.58,6330 h60
  text "Bottom Overlay" at 7000.49,6330 h60
  text ".Layer_Name" at 577,-858.49 h60
M13 Component Bodies Top:
  text ".Layer_Name" at 577,-858.49 h60
M14 Component Bodies Bottom:
  text ".Layer_Name" at 577,-858.49 h60
M15 Courtyards Top:
  text ".Layer_Name" at 577,-858.49 h60
M16 Courtyards Bottom:
  text ".Layer_Name" at 577,-858.49 h60
Drill Drawing:
  circle w10: c230.62,5615.83 r33.33
  lines w10: 197.29,5282.5 263.96,5282.5 263.96,5349.17 197.29,5349.17 197.29,5282.5 ; 197.29,5499.17 263.96,5499.17 230.62,5432.5 197.29,5499.17 ; 197.29,5749.17 213.96,5749.17 230.62,5732.5 247.29,5749.17 263.96,5749.17 247.29,5765.83 263.96,5782.5 247.29,5782.5 230.62,5799.17 213.96,5782.5 197.29,5782.5 213.96,5765.83 197.29,5749.17
  lines w15: 137.5,5237.5 10998.47,5237.5 ; 137.5,5837.5 10998.47,5837.5 ; 688.38,5087.5 688.38,5987.5 ; 1228.24,5087.5 1228.24,5987.5 ; 2327.92,5087.5 2327.92,5987.5 ; 2833.79,5087.5 2833.79,5987.5 ; 3567.59,5087.5 3567.59,5987.5 ; 5067.14,5087.5 5067.14,5987.5 ; 5656.99,5087.5 5656.99,5987.5 ; 6402.79,5087.5 6402.79,5987.5 ; 7432.49,5087.5 7432.49,5987.5 ; 8286.26,5087.5 8286.26,5987.5 ; 9619.86,5087.5 9619.86,5987.5 ; 137.5,5087.5 10998.47,5087.5 10998.47,5987.5 137.5,5987.5 137.5,5087.5
  text "Symbol" at 227.5,5882.5 h72
  text "Count" at 733.38,5882.5 h72
  text "Hole Size" at 1273.24,5882.5 h72
  text "Plated" at 2372.92,5882.5 h72
  text "Hole Type" at 2878.79,5882.5 h72
  text "Drill Layer Pair" at 3612.59,5882.5 h72
  text "Via/Pad" at 5112.14,5882.5 h72
  text "Pad Shape" at 5701.99,5882.5 h72
  text "Template" at 6447.79,5882.5 h72
  text "Description" at 7477.49,5882.5 h72
  text "Hole Tolerance (+)" at 8331.26,5882.5 h72
  text "Hole Tolerance (-)" at 9664.86,5882.5 h72
  text "4" at 733.38,5732.5 h60
  text "43.00mil (1.092mm)" at 1273.24,5732.5 h60
  text "PTH" at 2372.92,5732.5 h60
  text "Round" at 2878.79,5732.5 h60
  text "Top Layer - Bottom Layer" at 3612.59,5732.5 h60
  text "Pad" at 5112.14,5732.5 h60
  text "Rounded" at 5701.99,5732.5 h60
  text "c180h109" at 6447.79,5732.5 h60
  text "8" at 733.38,5582.5 h60
  text "67.00mil (1.702mm)" at 1273.24,5582.5 h60
  text "PTH" at 2372.92,5582.5 h60
  text "Round" at 2878.79,5582.5 h60
  text "Top Layer - Bottom Layer" at 3612.59,5582.5 h60
  text "Pad" at 5112.14,5582.5 h60
  text "Rounded" at 5701.99,5582.5 h60
  text "r229_279h170r100" at 6447.79,5582.5 h60
  text "12" at 733.38,5432.5 h60
  text "33.86mil (0.860mm)" at 1273.24,5432.5 h60
  text "NPTH" at 2372.92,5432.5 h60
  text "Round" at 2878.79,5432.5 h60
  text "Top Layer - Bottom Layer" at 3612.59,5432.5 h60
  text "Pad" at 5112.14,5432.5 h60
  text "Rounded" at 5701.99,5432.5 h60
  text "(Mixed)" at 6447.79,5432.5 h60
  text "1.97mil (0.050mm)" at 8331.26,5432.5 h60
  text "0.00mil (0.000mm)" at 9664.86,5432.5 h60
  text "40" at 733.38,5282.5 h60
  text "10.00mil (0.254mm)" at 1273.24,5282.5 h60
  text "PTH" at 2372.92,5282.5 h60
  text "Round" at 2878.79,5282.5 h60
  text "Top Layer - Bottom Layer" at 3612.59,5282.5 h60
  text "Via" at 5112.14,5282.5 h60
  text "Rounded" at 5701.99,5282.5 h60
  text "v51h25" at 6447.79,5282.5 h60
  text "64 Total" at 733.38,5132.5 h60
  text ".Layer_Name" at 577,-858.49 h60
M17 Embedded Cavity:
  text ".Layer_Name" at 577,-858.49 h60
M18 Embedded Assembly:
  text ".Layer_Name" at 577,-858.49 h60
M19 Embedded Keepout:
  text ".Layer_Name" at 577,-858.49 h60

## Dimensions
0,-400 to 1000,-400 on M2 Board Dimensions
0,0 to 310,1282 on M2 Board Dimensions
0,0 to 0,355 on M2 Board Dimensions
